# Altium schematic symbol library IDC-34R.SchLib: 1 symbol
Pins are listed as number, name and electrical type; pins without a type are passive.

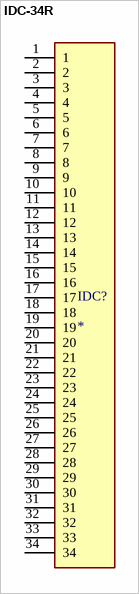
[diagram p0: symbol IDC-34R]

## IDC-34R
designator IDC?
IDC LOW PRO HDR 34P RA HT BLACK; MP: 1-1761682-1
footprint IDC-34R
pins: 1, 2, 3, 4, 5, 6, 7, 8, 9, 10, 11, 12, 13, 14, 15, 16, 17, 18, 19, 20, 21, 22, 23, 24, 25, 26, 27, 28, 29, 30, 31, 32, 33, 34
